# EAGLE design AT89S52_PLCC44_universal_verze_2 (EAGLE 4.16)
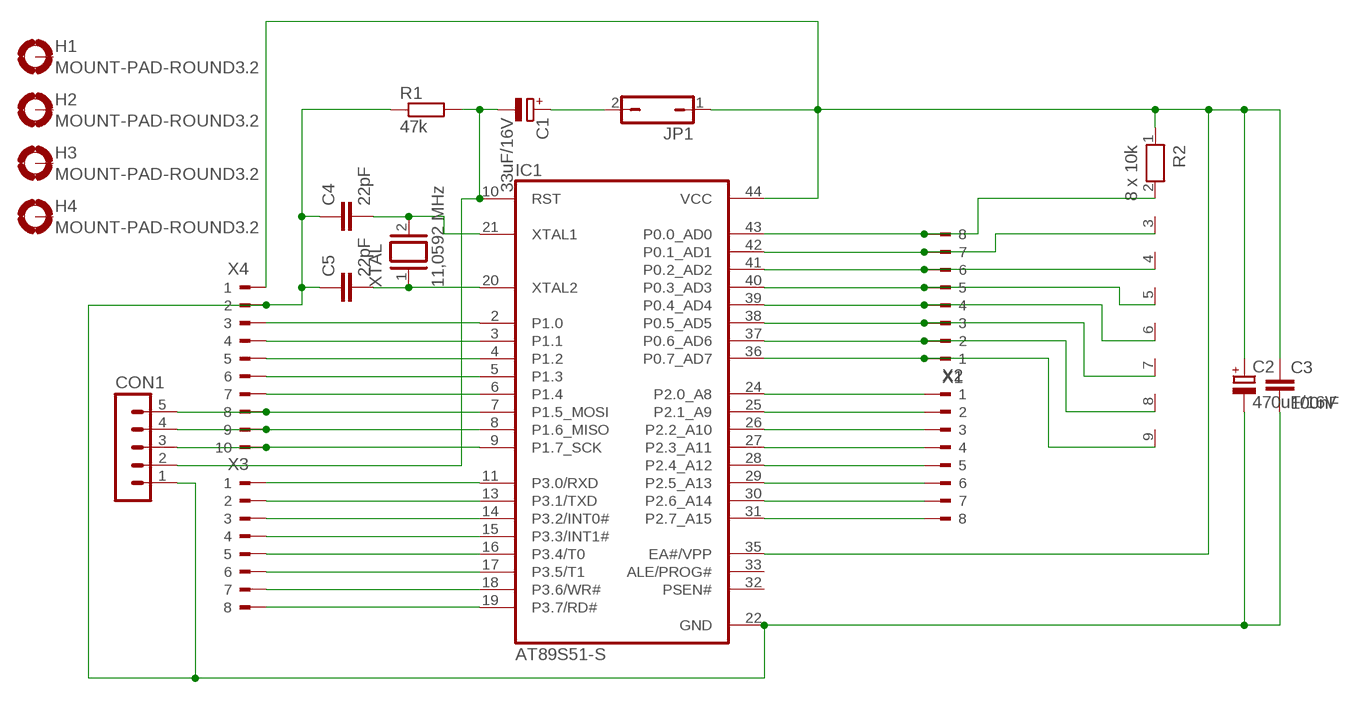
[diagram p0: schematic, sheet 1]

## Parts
C1  33uF/16V  CPOL-EUE2.5-7  [E2,5-7]
C2  470uF/16V  CPOL-EUE3.5-8  [E3,5-8]
C3  100nF  C-EU025-024X044  [C025-024X044]
C4  22pF  C-EU025-024X044  [C025-024X044]
C5  22pF  C-EU025-024X044  [C025-024X044]
CON1  MA05-1  [MA05-1]
H1  MOUNT-PAD-ROUND3.2  [3,2-PAD]
H2  MOUNT-PAD-ROUND3.2  [3,2-PAD]
H3  MOUNT-PAD-ROUND3.2  [3,2-PAD]
H4  MOUNT-PAD-ROUND3.2  [3,2-PAD]
IC1  AT89S51-S  [S44]
JP1  JP1Q  [JP1]
R1  47k  R-EU_0207/10  [0207/10]
R2  8 x 10k  RN08  [RN-9]
X1  90-8  [90-8]
X2  90-8  [90-8]
X3  90-8  [90-8]
X4  90-10  [90-10]
XTAL  11,0592 MHz  XTAL/S  [QS]

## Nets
N$1: IC1.2(P1.0) X4.3
N$2: CON1.3 IC1.9(P1.7_SCK) X4.10
N$3: IC1.31(P2.7_A15) X2.8
N$4: IC1.24(P2.0_A8) X2.1
N$5: IC1.11(P3.0/RXD) X3.1
N$6: IC1.19(P3.7/RD#) X3.8
N$7: IC1.43(P0.0_AD0) R2.2 X1.8
N$8: IC1.36(P0.7_AD7) R2.9 X1.1
N$9: IC1.3(P1.1) X4.4
N$10: IC1.4(P1.2) X4.5
N$11: IC1.5(P1.3) X4.6
N$12: IC1.6(P1.4) X4.7
N$13: CON1.5 IC1.7(P1.5_MOSI) X4.8
N$15: IC1.13(P3.1/TXD) X3.2
N$16: IC1.14(P3.2/INT0#) X3.3
N$17: IC1.15(P3.3/INT1#) X3.4
N$18: IC1.16(P3.4/T0) X3.5
N$19: IC1.17(P3.5/T1) X3.6
N$20: IC1.18(P3.6/WR#) X3.7
N$21: IC1.42(P0.1_AD1) R2.3 X1.7
N$22: IC1.41(P0.2_AD2) R2.4 X1.6
N$23: IC1.40(P0.3_AD3) R2.5 X1.5
N$24: IC1.39(P0.4_AD4) R2.6 X1.4
N$25: IC1.38(P0.5_AD5) R2.7 X1.3
N$26: IC1.37(P0.6_AD6) R2.8 X1.2
N$27: IC1.25(P2.1_A9) X2.2
N$28: IC1.26(P2.2_A10) X2.3
N$29: IC1.27(P2.3_A11) X2.4
N$30: IC1.28(P2.4_A12) X2.5
N$31: IC1.29(P2.5_A13) X2.6
N$32: IC1.30(P2.6_A14) X2.7
N$33: C5.2 IC1.20(XTAL2) XTAL.1
N$34: C4.2 IC1.21(XTAL1) XTAL.2
N$35: C2.- C3.2 C4.1 C5.1 CON1.1 IC1.22(GND) R1.1 X4.2
N$37: C2.+ C3.1 IC1.35(EA#/VPP) IC1.44(VCC) JP1.1 R2.1 X4.1
N$38: C1.- CON1.2 IC1.10(RST) R1.2
N$42: C1.+ JP1.2
N$43: CON1.4 IC1.8(P1.6_MISO) X4.9
Unconnected: H1.B3,2(MOUNT) H2.B3,2(MOUNT) H3.B3,2(MOUNT) H4.B3,2(MOUNT) IC1.32(PSEN#) IC1.33(ALE/PROG#)

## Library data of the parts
C1 C2 = rcl:CPOL-EU: POLARIZED CAPACITOR, European symbol
C3-C5 = rcl:C-EU: CAPACITOR, European symbol
CON1 = con-lstb:MA05-1: PIN HEADER
H1-H4 = holes:MOUNT-PAD-ROUND: MOUNTING PAD, round
IC1 = atmel:AT89S51-*: 8-bit Microcontroller with 4K BytesIn-System Programmable Flash Source: http://www.atmel.com/dyn/resources/prod_documents/doc2487.pdf
JP1 = jumper:JP1Q: JUMPER
R1 = rcl:R-EU_: RESISTOR, European symbol
R2 = resistor-net:RN08: RESISTOR NETWORK
X1-X3 = con-weidmueller-sl35:90-8: WEIDMUELLER CLAMP CONNECTOR
X4 = con-weidmueller-sl35:90-10: WEIDMUELLER CLAMP CONNECTOR
XTAL = special:XTAL/S: CRYSTAL

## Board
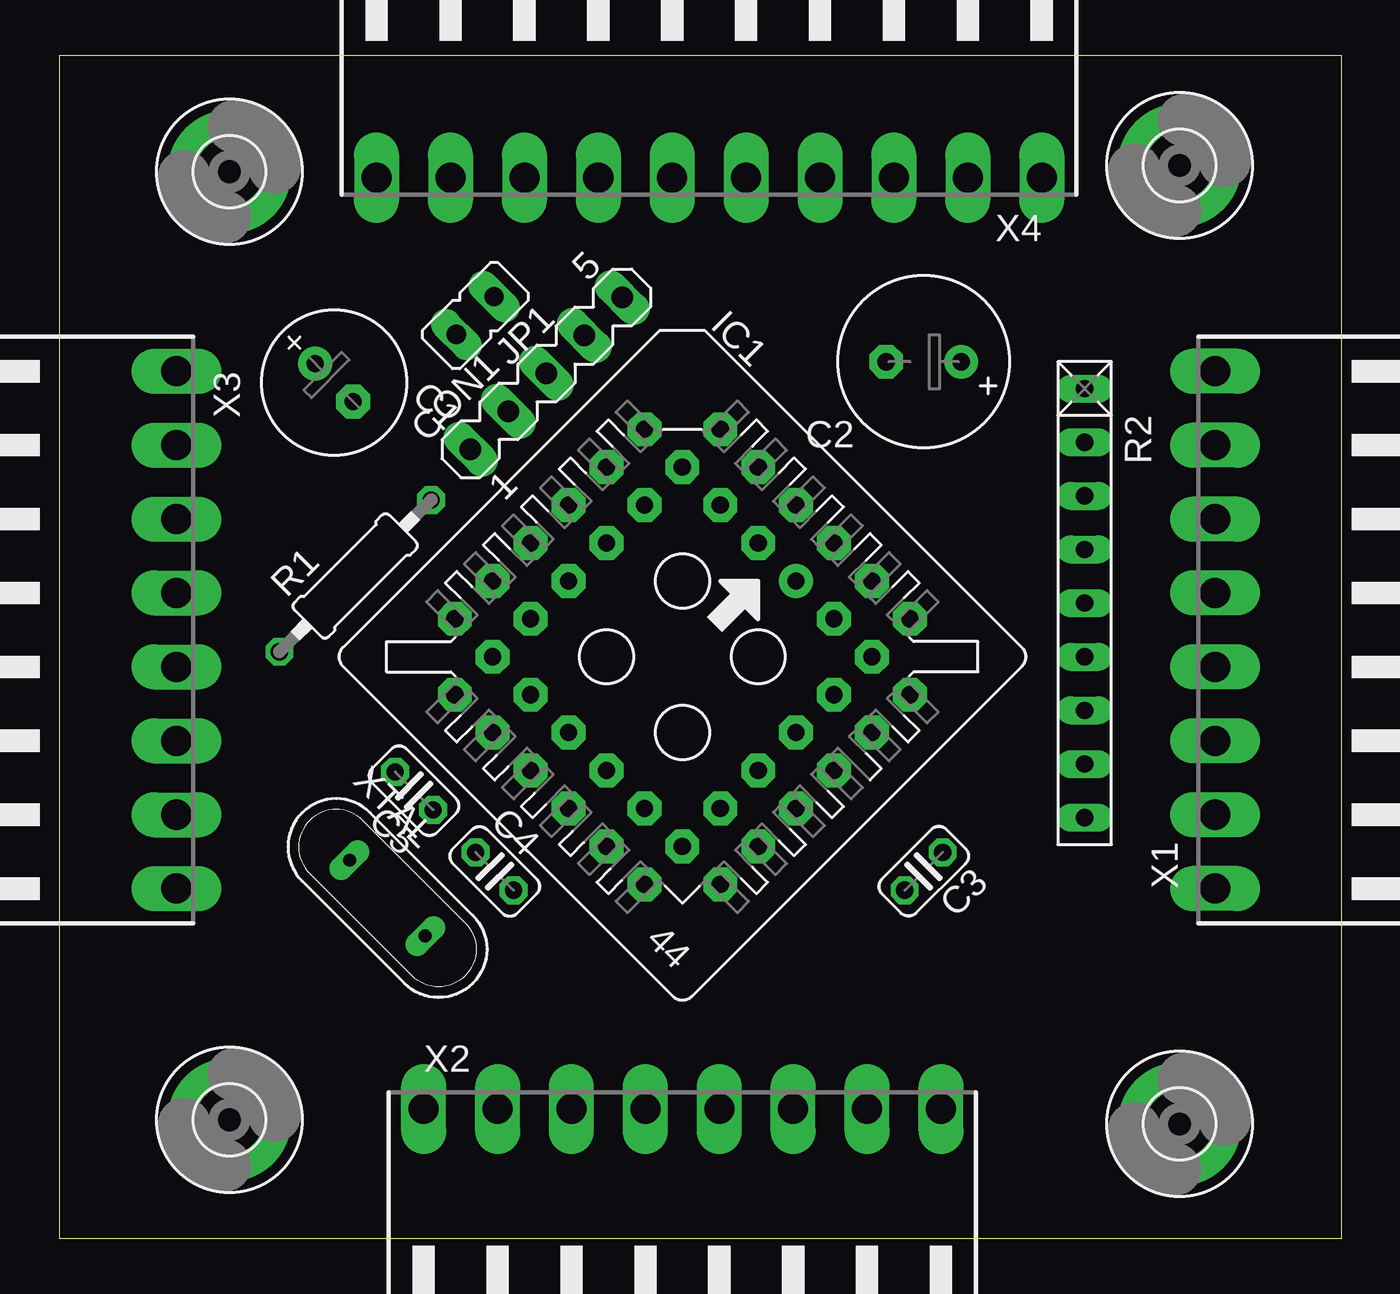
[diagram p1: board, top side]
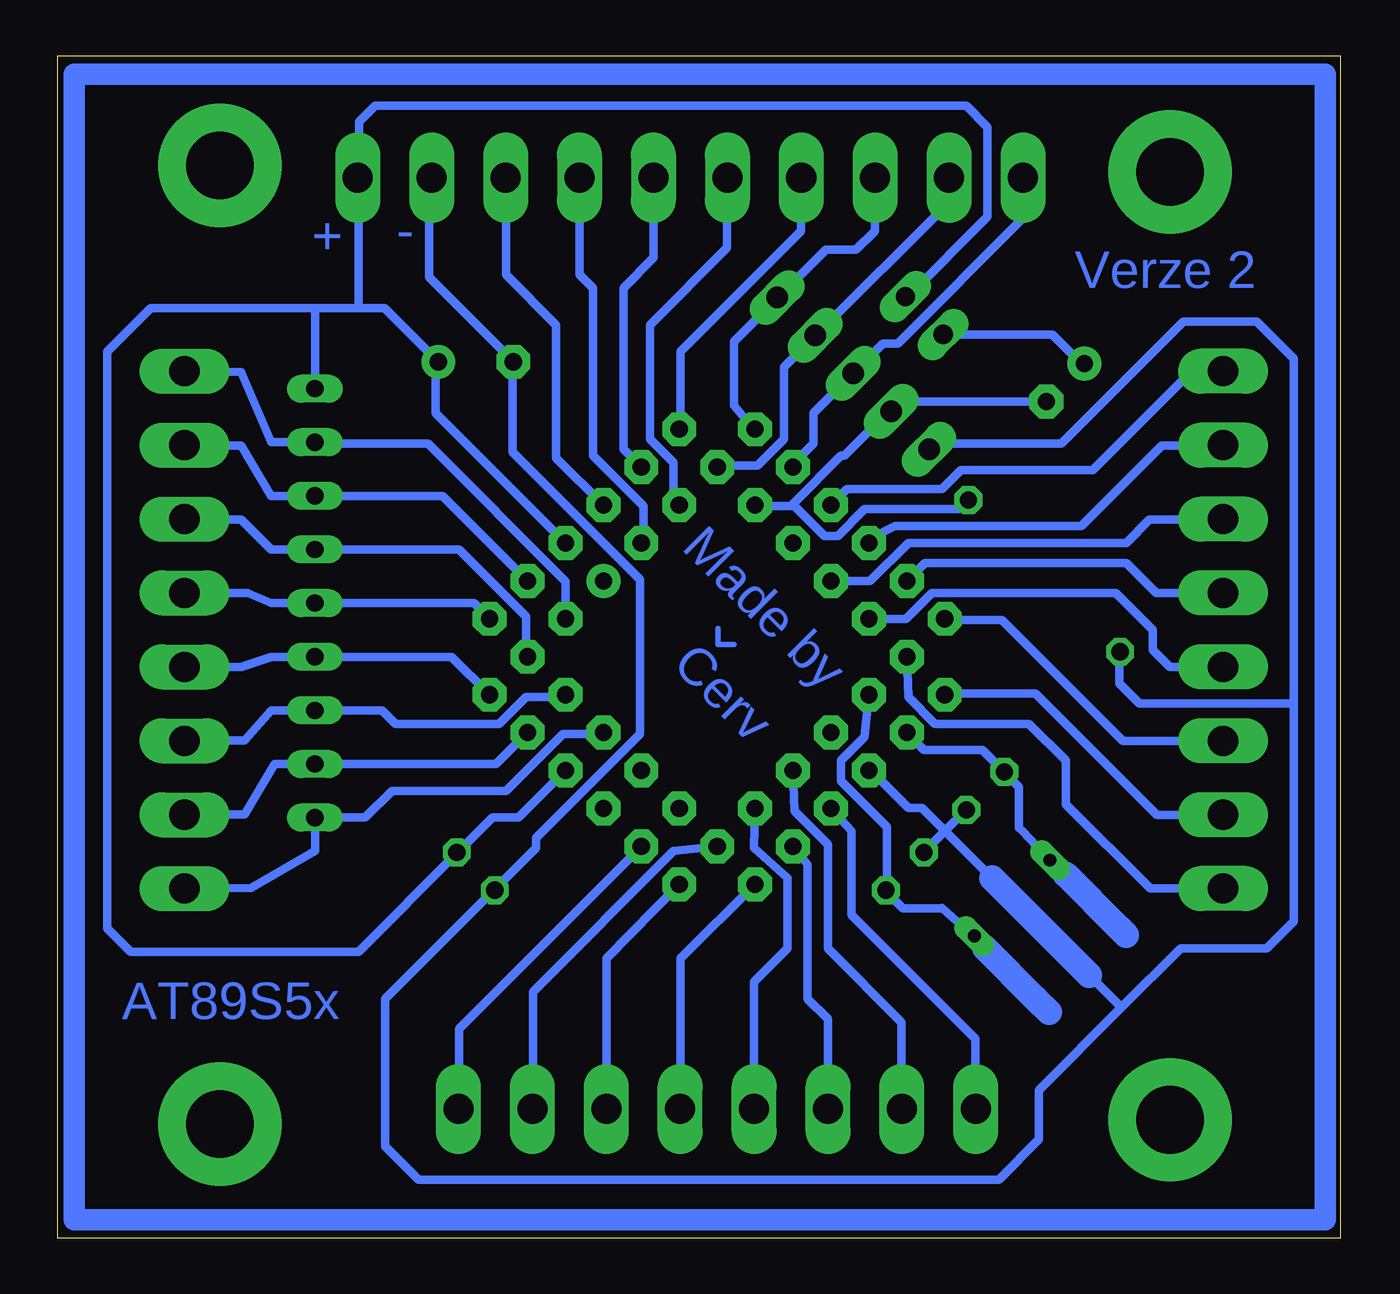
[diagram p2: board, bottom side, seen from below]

Size 60.75 x 56 mm. Coordinates in mm from the lower left corner, seen from the top.
Outline: 0,0 60.75,0 60.75,56 0,56 0,0
Copper layers (1*16): Top 0.035mm / dielectric 1.5mm / Bottom 0.035mm
Design rules "default": minimum track width 10mil, minimum drill 24mil, track to track 8mil, track to pad 8mil, pad to pad 8mil, via to via 8mil, smd to smd 8mil, copper to edge 40mil, drill to drill 8mil, minimum pad ring 10mil, minimum via ring 8mil, stop-mask expansion 4mil, vias tented up to drill 0mil, thermal gap 10mil

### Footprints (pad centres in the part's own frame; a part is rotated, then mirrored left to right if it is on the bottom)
E2,5-7 = drill 0.813 pad 1.6 round: + -1.27,0 | drill 0.813 pad 1.6 octagon: - 1.27,0
E3,5-8 = drill 0.813 pad 1.6 round: + -1.778,0 | drill 0.813 pad 1.6 octagon: - 1.778,0
C025-024X044 = drill 0.813 octagon: 1 -1.27,0; 2 1.27,0
MA05-1 = drill 1.016 long: 1 -5.08,0; 2 -2.54,0; 3 0,0; 4 2.54,0; 5 5.08,0
3,2-PAD = drill 3.2 pad 5.842 round: B3,2 0,0
S44 = drill 0.813 pad 1.6 round: 1 1.27,6.35 | drill 0.813 pad 1.6 octagon: 2 -1.27,8.89; 3 -1.27,6.35; 4 -3.81,8.89; 5 -3.81,6.35; 6 -6.35,8.89; 7 -8.89,6.35; 8 -6.35,6.35; 9 -8.89,3.81; 10 -6.35,3.81; 11 -8.89,1.27; 12 -6.35,1.27; 13 -8.89,-1.27; 14 -6.35,-1.27; 15 -8.89,-3.81; 16 -6.35,-3.81; 17 -8.89,-6.35; 18 -6.35,-8.89; 19 -6.35,-6.35; 20 -3.81,-8.89; 21 -3.81,-6.35; 22 -1.27,-8.89; 23 -1.27,-6.35; 24 1.27,-8.89; 25 1.27,-6.35; 26 3.81,-8.89; 27 3.81,-6.35; 28 6.35,-8.89; 29 8.89,-6.35; 30 6.35,-6.35; 31 8.89,-3.81; 32 6.35,-3.81; 33 8.89,-1.27; 34 6.35,-1.27; 35 8.89,1.27; 36 6.35,1.27; 37 8.89,3.81; 38 6.35,3.81; 39 8.89,6.35; 40 6.35,8.89; 41 6.35,6.35; 42 3.81,8.89; 43 3.81,6.35; 44 1.27,8.89
JP1 = drill 0.914 long: 1 0,-1.27; 2 0,1.27
0207/10 = drill 0.813 octagon: 1 -5.08,0; 2 5.08,0
RN-9 = drill 0.813 long: 1 -10.16,0; 2 -7.62,0; 3 -5.08,0; 4 -2.54,0; 5 0,0; 6 2.54,0; 7 5.08,0; 8 7.62,0; 9 10.16,0
90-8 = drill 1.422 long: 1 -12.25,5.25; 2 -8.75,5.25; 3 -5.25,5.25; 4 -1.75,5.25; 5 1.75,5.25; 6 5.25,5.25; 7 8.75,5.25; 8 12.25,5.25
90-10 = drill 1.422 long: 1 -15.75,5.25; 2 -12.25,5.25; 3 -8.75,5.25; 4 -5.25,5.25; 5 -1.75,5.25; 6 1.75,5.25; 7 5.25,5.25; 8 8.75,5.25; 9 12.25,5.25; 10 15.75,5.25
QS = drill 0.61 long: 1 -2.54,0; 2 2.54,0

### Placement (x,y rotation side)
C1  13.03,40.53 315 top
C2  40.95,41.51 180 top
C3  40.95,17.38 225 top
C4  20.63,17.38 315 top
C5  16.82,21.19 135 top
CON1  23.08,40.96 45 top
H1  8.07,50.51 0 top
H2  53.07,50.81 0 top
H3  8.07,5.61 0 top
H4  53.07,5.41 0 top
IC1  29.52,27.54 315 top
JP1  19.71,43.7 135 top
R1  14.03,31.37 45 top
R2  48.57,30.08 270 top
X1  60,28.81 90 top
X2  29.52,0.87 0 top
X3  0.31,28.81 270 top
X4  30.79,55.48 180 top
XTAL  15.55,16.11 315 top

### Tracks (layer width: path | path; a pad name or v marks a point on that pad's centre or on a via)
N$1
  Bottom 0.406: IC1.2 37.14,36.96 37.14,43.26 39.52,45.64 39.52,50.24 39.53,50.24 X4.3
N$2
  Bottom 0.406: CON1.3 23.01,41.03 | 23.01,41.03 24.76,39.29 24.97,39.08 24.97,37.63 25.97,36.63 25.97,36.56 IC1.9 | 23.01,41.03 21.66,42.38 20.97,42.38 14.97,48.38 14.97,50.16 X4.10
N$3
  Bottom 0.406: IC1.31 41.74,9.92 41.74,6.11 X2.8
N$4
  Bottom 0.406: IC1.24 23.17,19.29 23.17,15.32 17.3,9.44 17.3,6.11 X2.1
N$5
  Bottom 0.406: IC1.11 23.38,35.48 18.87,35.48 17.97,36.38 11.72,36.38 6.97,41.13 5.63,41.13 X3.1
N$6
  Bottom 0.406: IC1.19 20.47,25.64 19.2,24.37 14.76,24.37 13.01,22.62 13.01,20.55 9.02,16.56 X3.8
N$7
  Bottom 0.406: X1.8 52.06,41.03 50.63,37.7 R2.2 48.54,37.7 48.47,37.63 43.22,37.63 36.7,31.11 IC1.43
N$8
  Bottom 0.406: IC1.36 34.97,23.89 36.82,23.89 39.52,21.19 44.92,21.19 46.19,19.92 R2.9 48.57,18.33 51.59,16.59 X1.1
N$9
  Bottom 0.406: IC1.3 33.01,33.03 33.01,34.68 35.39,37.07 35.39,45 36.03,45.64 36.03,50.24 | 36.03,50.24 | 36.03,50.24 X4.4
N$10
  Bottom 0.406: IC1.4 33.96,37.37 33.96,45 32.54,46.43 X4.5 | 32.54,50.24 X4.5 | X4.5
N$11
  Bottom 0.406: IC1.5 31.58,34.99 31.58,36.75 32.7,37.86 32.7,43.26 29.04,46.91 X4.6 | 29.04,50.24 X4.6 | X4.6
N$12
  Bottom 0.406: X4.7 25.55,50.22 25.55,47.7 31.27,41.99 31.27,38.34 31.3,38.34 IC1.6
N$13
  Bottom 0.406: IC1.7 27.77,38.34 28.73,39.45 28.73,42.46 CON1.5 26.66,44.53 24.37,46.82 22.94,46.82 22.06,47.7 X4.8
N$15
  Bottom 0.406: IC1.13 22.16,33.18 21.11,33.73 12.26,33.73 8.45,37.54 5.55,37.54 X3.2
N$16
  Bottom 0.406: IC1.14 22.28,31.13 20.47,32.94 10.15,32.94 9.04,34.05 5.55,34.05 X3.3
N$17
  Bottom 0.406: IC1.15 19.68,31.98 10.15,31.98 8.72,30.56 X3.4
N$18
  Bottom 0.406: IC1.16 20.58,29.34 19.36,30.56 10.63,30.56 8.88,28.81 8.88,27.86 8.09,27.06 X3.5
N$19
  Bottom 0.406: X3.6 10.3,23.56 16.03,29.29 18.73,29.29 18.74,29.3 IC1.17
N$20
  Bottom 0.406: X3.7 8.7,20.06 14.44,25.79 18.73,25.79 18.74,25.78 IC1.18
N$21
  Bottom 0.406: IC1.42 42.53,35.16 R2.3 50.63,35.16 52.06,37.54 54.6,37.54 X1.7
N$22
  Bottom 0.406: IC1.41 38.57,27.61 38.57,29.45 41.74,32.62 R2.4 50.63,32.62 52.06,34.05 54.76,34.05 X1.6
N$23
  Bottom 0.406: IC1.40 41.04,30.08 R2.5 50.63,30.08 51.75,30.56 X1.5
N$24
  Bottom 0.406: IC1.39 42.09,27.54 R2.6 50.63,27.54 52.06,27.06 X1.4
N$25
  Bottom 0.406: IC1.38 36.81,25.64 38.57,25.64 39.84,24.37 44.76,24.37 45.39,25 R2.7 50.63,25 51.9,23.57 54.92,23.57 X1.3
N$26
  Bottom 0.406: IC1.37 39.99,22.46 R2.8 50.47,22.46 51.9,20.08 54.76,20.08 X1.2
N$27
  Bottom 0.406: IC1.25 25.87,20.24 24.28,18.65 24.28,13.73 20.79,10.24 20.79,6.11 X2.2
N$28
  Bottom 0.406: IC1.26 25.23,17.7 25.23,11.35 24.28,10.4 24.28,6.11 X2.3
N$29
  Bottom 0.406: IC1.27 27.77,18.49 26.19,17.06 26.19,13.73 27.77,12.14 27.77,5.95 X2.4
N$30
  Bottom 0.406: IC1.28 31.27,13.25 31.27,6.11 X2.5
N$31
  Bottom 0.406: IC1.29 34.76,13.25 34.76,6.11 X2.6
N$32
  Bottom 0.406: IC1.30 31.58,18.33 38.25,11.67 38.25,6.11 X2.7
N$33
  Bottom 0.406: XTAL.1 15.07,19.29 15.22,19.43 15.22,21.38 15.97,22.13 | C5.2 15.87,21.98 | C5.2 15.87,22.14 | IC1.20 19.72,23.13 16.97,23.13 15.97,22.13 | C5.2 15.72,21.89 15.72,21.88 15.97,22.13 | 15.97,22.13 15.96,22.13 C5.2
N$34
  Bottom 0.406: XTAL.2 17.45,14.36 18.88,15.63 18.89,15.63 20.72,15.63 21.47,16.38 21.63,16.38 | IC1.21 22.53,23.73 23.65,22.62 23.65,21.67 21.47,19.49 21.47,16.54 C4.2 | C4.2 21.58,16.43 | 21.72,16.38 21.63,16.38 | 21.63,16.38 C4.2
N$35
  Bottom 0.406: X4.2 43.17,50.1 43.17,45.51 C2.- 39.2,41.48 39.2,37.22 33.17,31.19 33.17,23.89 38.09,18.97 38.09,18.49 40.16,16.43 | C4.1 19.68,18.33 18.73,19.29 | 18.73,19.29 C5.1 18.73,19.29 | 18.73,19.29 16.03,16.59 | R1.1 10.47,27.75 10.47,26.27 9.52,25.32 2.21,25.32 | 18.73,19.29 | 2.21,25.32 2.21,15 3.48,13.73 7.56,13.73 10.37,10.93 | 2.21,25.32 2.21,41.67 3.96,43.41 7.43,43.41 13.22,37.63 19.22,37.63 CON1.1 | 10.37,10.93 14.28,7.01 14.28,4.68 16.19,2.78 43.65,2.78 45.24,4.36 45.24,11.35 40.16,16.43 | 40.16,16.43 40.16,16.59 C3.2 40.11,16.43 40.16,16.43 | 10.37,10.93 18.73,19.29 | 40.16,16.43 40,16.43 | 18.73,19.29 19.82,20.38 20.47,20.38 22.22,22.13 22.36,22.13 | 22.36,22.13 22.47,22.13 | 22.36,22.13 IC1.22
  Bottom 1.219: 16.5,17.06 16.03,16.59 11.9,12.46
N$36
  Bottom 1.016: 59.97,0.88 59.97,55.13 0.72,55.13 0.72,0.88 59.97,0.88
N$37
  Bottom 0.406: IC1.44 42.86,39.08 42.86,41.51 C2.+ 45.27,44.05 46.51,44.05 | IC1.35 38.94,19.92 40.16,19.92 41.9,18.17 | 48.57,44.05 56.35,44.05 58.41,41.99 58.41,14.68 57.3,13.57 46.51,13.57 41.9,18.17 | 48.57,44.05 46.51,44.05 | 48.57,44.05 R2.1 | 41.9,18.17 41.9,18.22 C3.1 | 46.51,44.05 46.51,50.2 X4.1 46.47,50.16 | JP1.1 20.58,44.63 20.47,44.63 16.72,48.38 16.72,52.63 17.72,53.63 45.72,53.63 46.47,52.88 46.47,50.16 | 46.47,50.16 46.47,50.13
N$38
  Bottom 0.406: IC1.10 27.68,34.68 26.03,34.68 25.87,34.84 | 25.87,34.84 23.65,37.07 23.49,37.07 21.42,39.13 21.27,39.13 | 21.27,39.13 21.27,39.15 CON1.2 | R1.2 18.06,34.53 22.53,34.53 23.8,33.26 24.44,33.26 25.87,34.68 25.87,34.84 | 21.27,39.13 20.76,39.63 13.72,39.63 C1.-
N$39
  Bottom 1.219: 13.01,17.22 10.47,14.68 | 10.47,14.68 10.31,14.52 | 10.47,14.68 10.15,14.36
N$40
  Bottom 1.219: 16.82,13.73 14.44,11.35 13.8,10.71
N$41
  Bottom 0.254: 28.72,28.13 29.47,28.13 29.47,28.88
N$42
  Bottom 0.406: C1.+ 12.17,41.43 12.22,41.38 13.64,42.8 JP1.2
N$43
  Bottom 0.406: IC1.8 29.45,36.59 27.62,36.59 26.34,37.86 26.34,41.26 24.84,42.76 CON1.4 18.59,49.01 18.47,50.26 X4.9

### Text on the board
Bottom: - | + | Verze 2 | Made by | Cerv | AT89S5x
